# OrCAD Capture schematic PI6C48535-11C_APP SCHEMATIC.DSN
size B; title: PI6C48535-11C Application Schematic; rev: 1.0; note: Diodes Inc. Clock IC Application Engineering
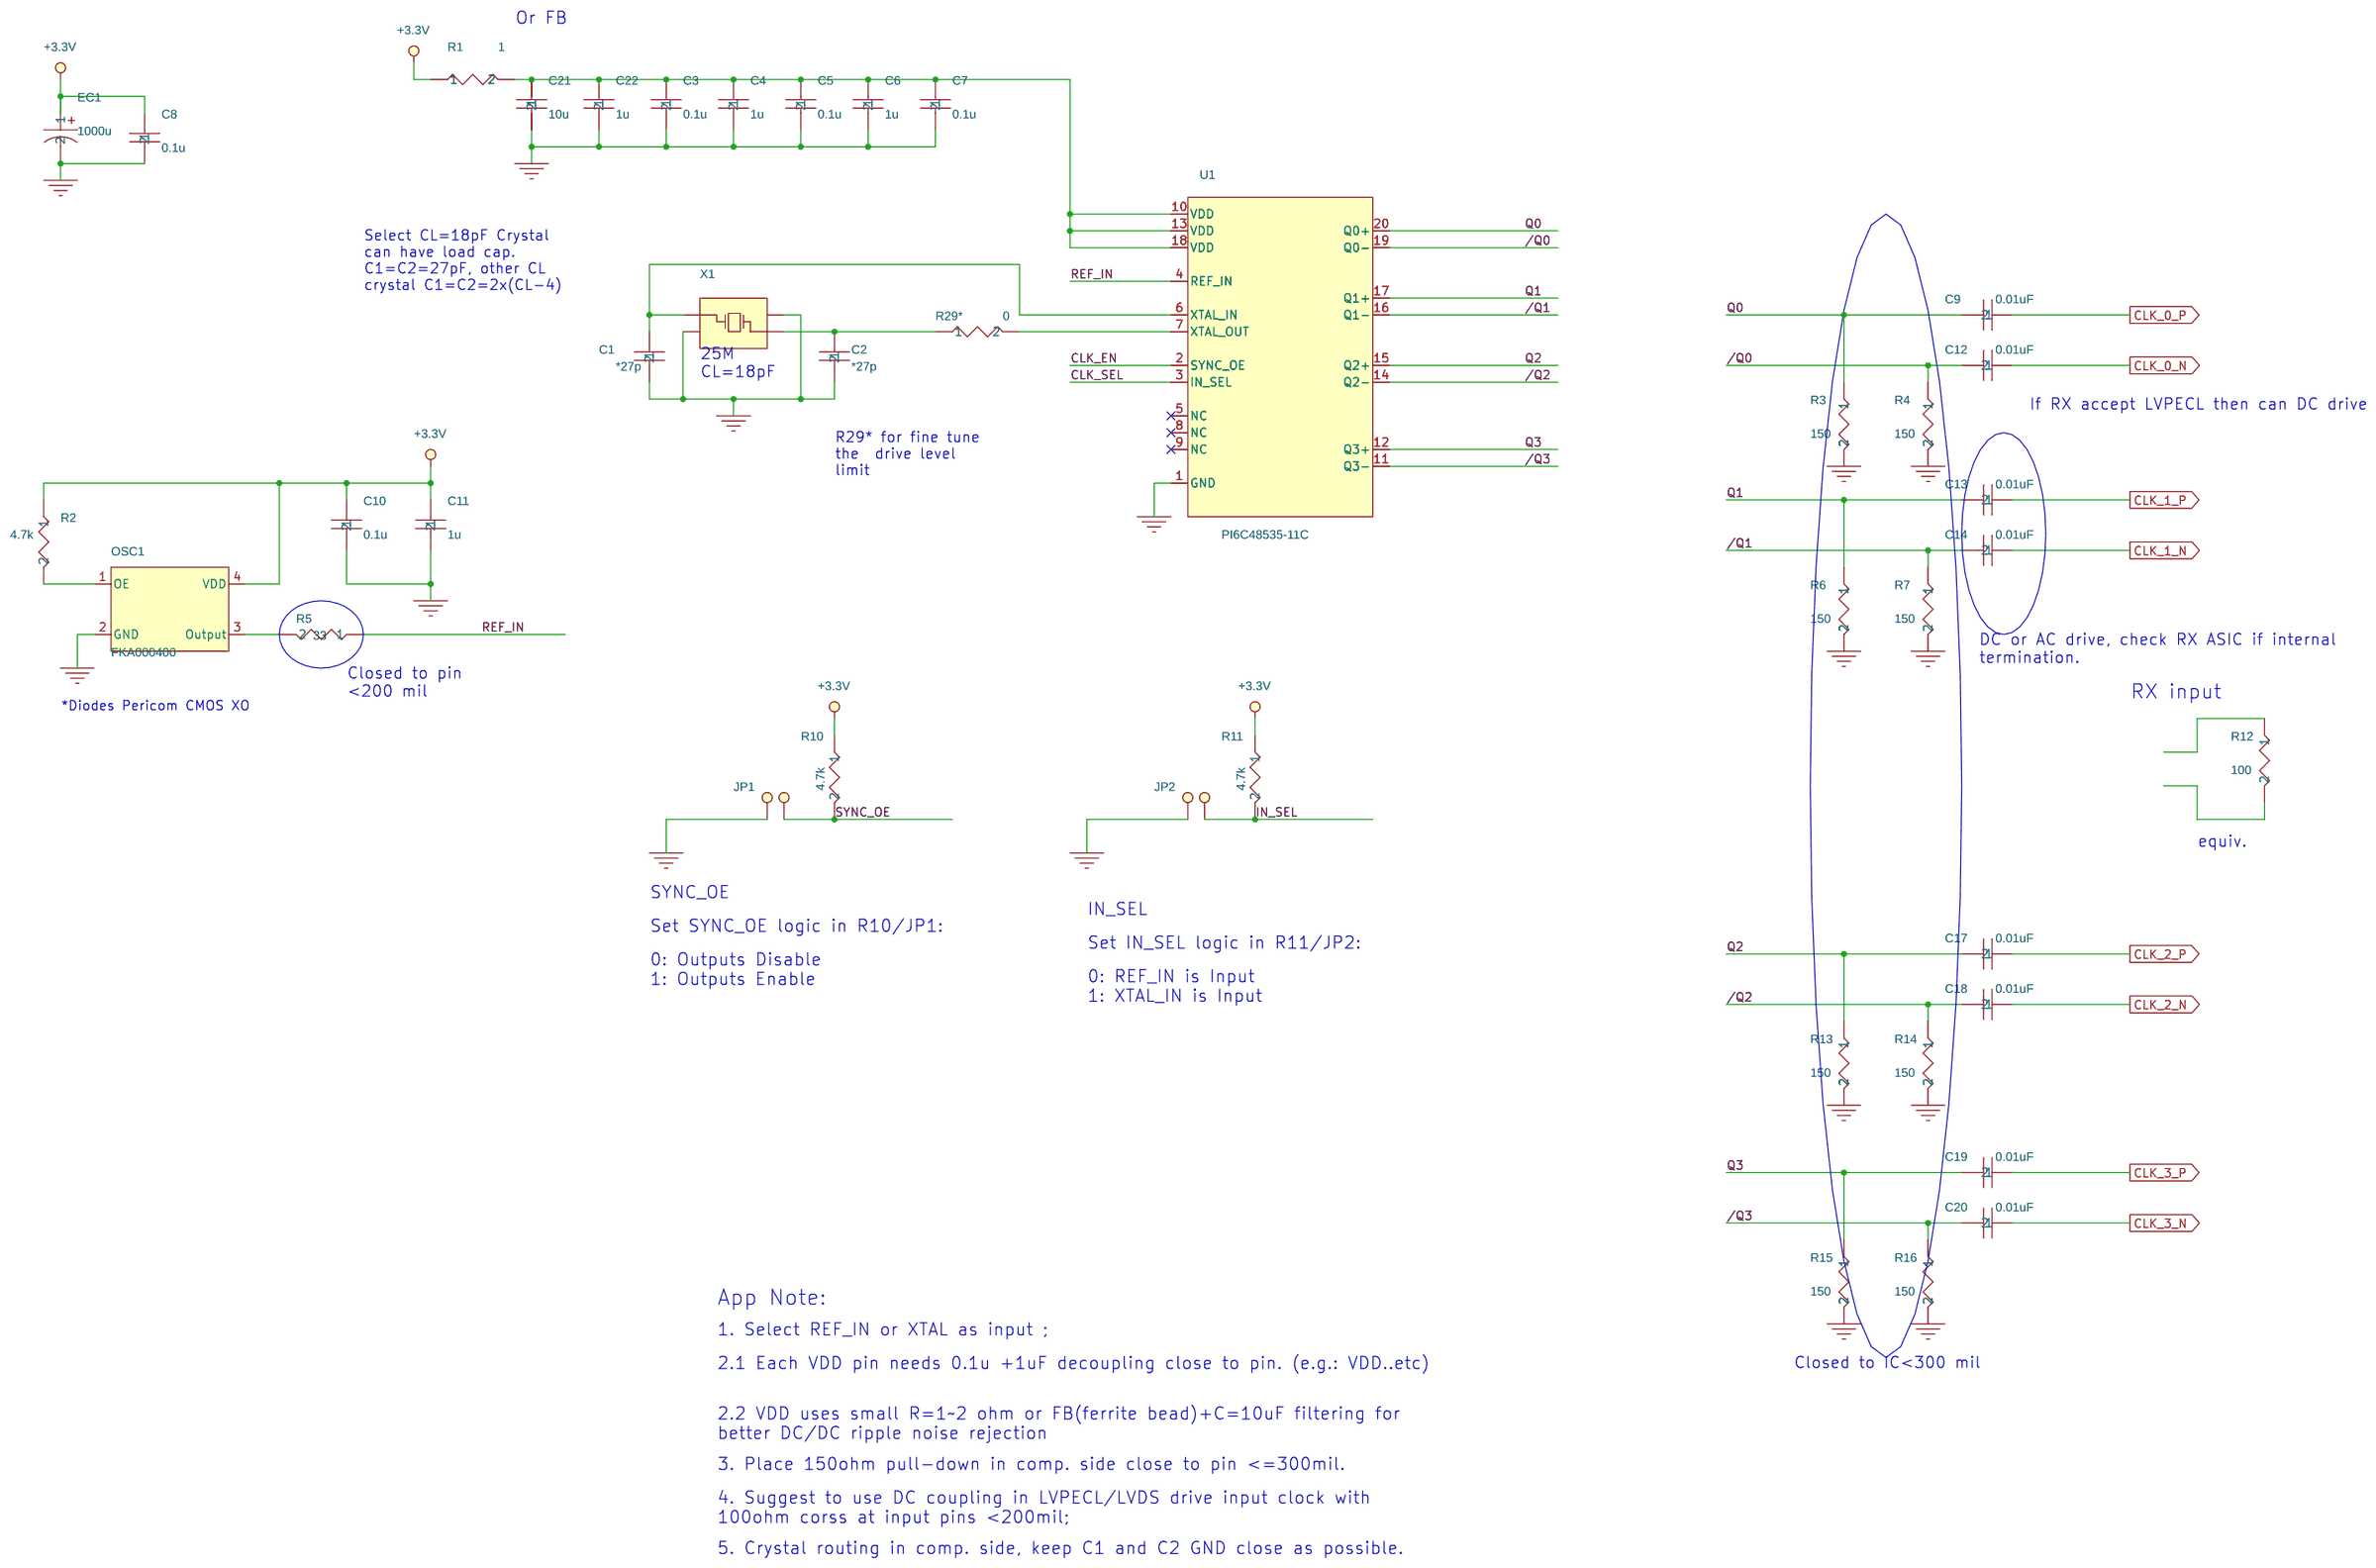
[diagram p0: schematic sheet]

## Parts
C1  *27p  [CC_0402]
C2  *27p  [CC_0402]
C3  0.1u  [CC_0402]
C4  1u  [CC_0805]
C5  0.1u  [CC_0402]
C6  1u  [CC_0805]
C7  0.1u  [CC_0402]
C8  0.1u  [CC_0402]
C9  0.01uF  [CC_0402]
C10  0.1u  [CC_0402]
C11  1u  [CC_0402]
C12  0.01uF  [CC_0402]
C13  0.01uF  [CC_0402]
C14  0.01uF  [CC_0402]
C17  0.01uF  [CC_0402]
C18  0.01uF  [CC_0402]
C19  0.01uF  [CC_0402]
C20  0.01uF  [CC_0402]
C21  10u  [CC_0805]
C22  1u  [CC_0805]
EC1  1000u  [CAP1000UF]
JP1  2x1 Pin Header  [2x1 Pin Header]
JP2  2x1 Pin Header  [2x1 Pin Header]
OSC1  FKA000400  [CYRSTAL-3_2X2_5MM]
R1  1  [R_0402]
R2  4.7k  [R_0402]
R3  150  [R_0402]
R4  150  [R_0402]
R5  33  [R_0402]
R6  150  [R_0402]
R7  150  [R_0402]
R10  4.7k  [R_0402]
R11  4.7k  [R_0402]
R12  100  [R_0402]
R13  150  [R_0402]
R14  150  [R_0402]
R15  150  [R_0402]
R16  150  [R_0402]
R29*  0  [R_0402]
U1  PI6C48535-11C
X1  Crystal_4P_SMD  [CYRSTAL@SM4]

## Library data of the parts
C1 = C_0.1u_0402_6
C2 = C_0.1u_0402
C3 = C_0.1u_0402_5
C4 = C_1.0u_0805
C5 = C_0.1u_0402_2
C6 = C_1.0u_0805_1
C7 = C_0.1u_0402_7
C8 = C_0.1u_0402_1
C9 = C_10n_0402_1
C10 = C_0.1u_0402_3
C11 = C_0.1u_0402_4
C12 = C_10n_0402_5
C13 = C_10n_0402_4
C14 = C_10n_0402_7
C17 = C_10n_0402_6
C18 = C_10n_0402
C19 = C_10n_0402_3
C20 = C_10n_0402_2
C21 = C_1.0u_0805_2
C22 = C_1.0u_0805_3
EC1 = C_alum_1000u
JP1 JP2 = 2x1_Pin_Header
OSC1 = UX3AA00003_0
R1 = R_0402_1
R2 = R_0402_2
R3 = R_0_7
R4 = R_0_3
R5 = R_0402_5
R6 = R_0_6
R7 = R_0_2
R10 = R_0402_3
R11 = R_0402
R12 = R_0_1
R13 = R_0
R14 = R_0_8
R15 = R_0_5
R16 = R_0_4
R29* = R_0402_4
U1 = PI6C4911504-03_5
X1 = Crystal_4P_SMD

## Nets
+3.3V: C8.1 C10.1 C11.1 EC1.1 OSC1.4(VDD) R1.1 R2.1 R10.1 R11.1
GND: C1.2 C2.2 C3.2 C4.2 C5.2 C6.2 C7.2 C8.2 C10.2 C11.2 C21.2 C22.2 EC1.2 JP1.1 JP2.1 OSC1.2(GND) R3.2 R4.2 R6.2 R7.2 R13.2 R14.2 R15.2 R16.2 U1.1(GND) X1.2 X1.4
/Q0: C12.2 R4.1 U1.19(Q0-)
/Q1: C14.2 R7.1 U1.16(Q1-)
/Q2: C18.2 R14.1 U1.14(Q2-)
/Q3: C20.2 R16.1 U1.11(Q3-)
CLK_0_N: C12.1
CLK_0_P: C9.1
CLK_1_N: C14.1
CLK_1_P: C13.1
CLK_2_N: C18.1
CLK_2_P: C17.1
CLK_3_N: C20.1
CLK_3_P: C19.1
CLK_EN: U1.2(SYNC_OE)
CLK_SEL: U1.3(IN_SEL)
IN_SEL: JP2.2 R11.2
Q0: C9.2 R3.1 U1.20(Q0+)
Q1: C13.2 R6.1 U1.17(Q1+)
Q2: C17.2 R13.1 U1.15(Q2+)
Q3: C19.2 R15.1 U1.12(Q3+)
REF_IN: R5.1 U1.4(REF_IN)
SYNC_OE: JP1.2 R10.2
N4605837: C3.1 C4.1 C5.1 C6.1 C7.1 C21.1 C22.1 R1.2 U1.10(VDD) U1.13(VDD) U1.18(VDD)
N4623138: OSC1.1(OE) R2.2
N4623162: OSC1.3(Output) R5.2
N4627097: C1.1 U1.6(XTAL_IN) X1.3
N4627117: C2.1 R29*.1 X1.1
N4628713: R29*.2 U1.7(XTAL_OUT)

Not connected (* = marked no-connect by the designer): R12 1 2; U1 5(NC)* 8(NC)* 9(NC)*

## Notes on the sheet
- Or FB
- Select CL=18pF Crystal
  can have load cap.
  C1=C2=27pF, other CL
  crystal C1=C2=2x(CL-4)
- 25M
  CL=18pF
- If RX accept LVPECL then can DC drive
- R29* for fine tune
  the  drive level
  limit
- DC or AC drive, check RX ASIC if internal
  termination.
- Closed to pin
  <200 mil
- RX input
- *Diodes Pericom CMOS XO
- equiv.
- SYNC_OE
- IN_SEL
- Set SYNC_OE logic in R10/JP1:
- 0: Outputs Disable
  1: Outputs Enable
- Set IN_SEL logic in R11/JP2:
- 0: REF_IN is Input
  1: XTAL_IN is Input
- App Note:
- 1. Select REF_IN or XTAL as input ;
- 2.1 Each VDD pin needs 0.1u +1uF decoupling close to pin. (e.g.: VDD..etc)
- Closed to IC<300 mil
- 2.2 VDD uses small R=1~2 ohm or FB(ferrite bead)+C=10uF filtering for
  better DC/DC ripple noise rejection
- 3. Place 150ohm pull-down in comp. side close to pin <=300mil.
- 4. Suggest to use DC coupling in LVPECL/LVDS drive input clock with
  100ohm corss at input pins <200mil;
- 5. Crystal routing in comp. side, keep C1 and C2 GND close as possible.
